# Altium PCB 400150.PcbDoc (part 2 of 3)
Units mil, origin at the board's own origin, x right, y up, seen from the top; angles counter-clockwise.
Board outline 4000 x 2500 mil, 4 copper layers (Top Layer, Mid-Layer 1, Mid-Layer 2, Bottom Layer), stack 62.293 mil thick; 200 components, 153 nets, 913 pads, 613 vias.
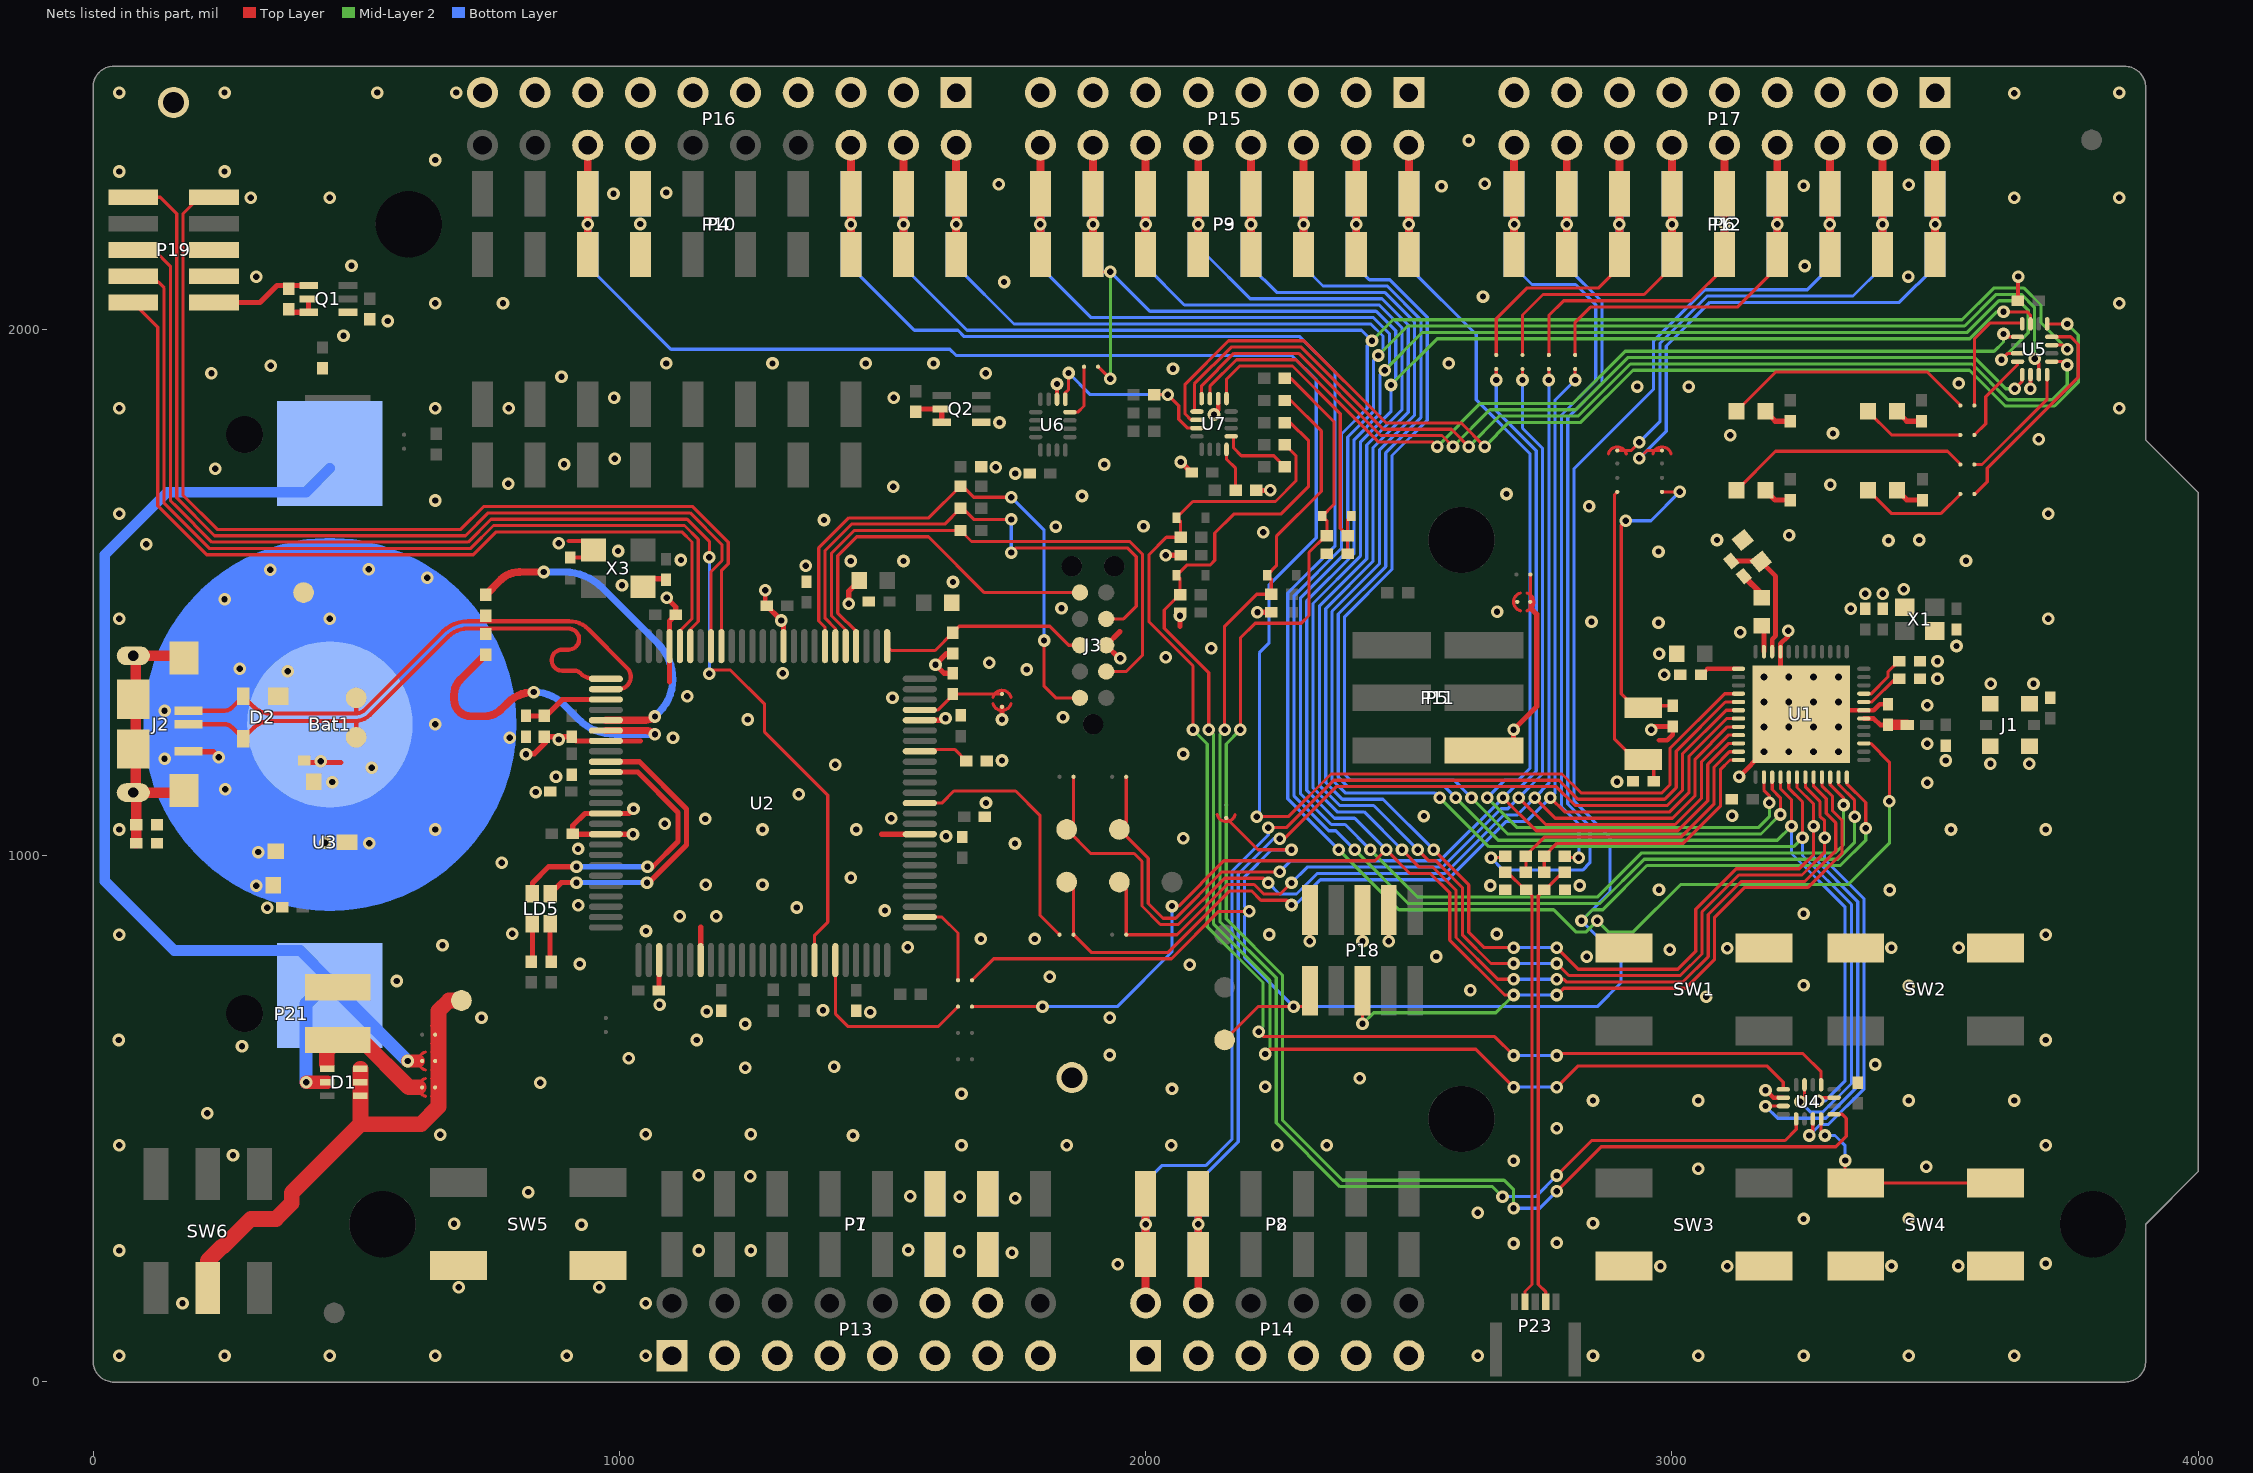
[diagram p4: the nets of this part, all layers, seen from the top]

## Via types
v1: diameter 24, hole 12, Top Layer to Bottom Layer, tented both sides, 576 vias
v2: diameter 24, hole 12, Top Layer to Bottom Layer, 21 vias
v3: diameter 25.98, hole 12.99, Top Layer to Bottom Layer, tented both sides, 16 vias

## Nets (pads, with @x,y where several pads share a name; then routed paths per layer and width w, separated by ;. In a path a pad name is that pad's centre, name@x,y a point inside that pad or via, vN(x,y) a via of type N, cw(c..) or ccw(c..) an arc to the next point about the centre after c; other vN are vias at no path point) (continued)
BUTTON4: SW4.1 U4.12 | length 425.6
  Top Layer w6: U4.12@3283.29,499.52 3283.29,475.38 v1(3290.66,468) ; v1(3329.02,420.63) 3329.02,396.63 3348.02,377.63 SW4.1@3613.77,377.63
  Bottom Layer w6: v1(3290.66,468) 3309.65,468 3329.02,448.63 v1(3329.02,420.63)
BUTTON4_EXT: C51.1 D6.3 R43.1 U7.5 | length 612.5
  Top Layer w6: U7.5@2153.56,1868.23 2153.56,1905.02 2178.53,1930 2278.99,1930 2369.75,1839.24 2369.75,1621.71 R43.1@2383.76,1607.69 ; C51.1@2383.76,1573.69 R43.1@2383.76,1607.69 ; D6.3@2390.86,1645 2383.76,1637.9 R43.1@2383.76,1607.69
CTS: SB22.2 U2.38 | length 499.2
  Top Layer w6: U2.38@1570.83,1099.6 1612.55,1099.6 1635.55,1122.6 1753.01,1122.6 1799,1076.6 1798.99,887.01 SB22.2@1836.4,849.6
DEC1: C4.1 U1.1 | length 76
  Top Layer w8: C4.1@3055.31,1342.92 3067.16,1354.77 U1.1@3126.37,1354.77
DEC2: C6.1 U1.32 | length 88.3
  Top Layer w6: U1.32@3364.56,1291.78 3379.76,1291.78 3424.14,1336.16 C6.1@3434.46,1336.16
DEC3: C7.1 U1.33 | length 96
  Top Layer w6: U1.33@3364.56,1307.53 3378.54,1307.53 3410.46,1339.46 3410.46,1349.35 C7.1@3429.52,1368.41
DEC4: C10.2 L3.1 U1.46 | length 241.3
  Top Layer w9: L3.1@3112.48,1559.49 C10.2@3167.89,1559.48 ; C10.2@3168.58,1558.8 3196.71,1530.66 3196.71,1417.47 3190.35,1411.11 U1.46@3190.35,1387.25
DFSD_N: R14.1 U2.80 | length 645
  Top Layer w13.78: 810,1538.6 v1(856.61,1538.6) ; U2.80@974.38,1257.18 1048.61,1257.18 ; 1050.33,1257.18 ccw(c1050.33,1281.62) v1@1067.61,1264.34
  Top Layer w15: R14.1@746.01,1495.22 774.82,1524.03 cw(c810,1488.84) 810,1538.6
  Bottom Layer w13.78: v1(856.61,1538.6) 896.18,1538.6 cw(c896.18,1438.6) 966.9,1509.31 1073.32,1402.88 cw(c1005.04,1334.6) 1101.61,1334.6 cw(c1013.82,1334.6) 1075.89,1272.53 v1(1067.61,1264.24)
DFSD_P: R13.1 U2.81 | length 642.8
  Top Layer w13.78: U2.81@974.38,1237.39 1049.61,1237.39 ; 1050.33,1237.39 cw(c1050.33,1212.96) v1@1067.61,1230.24
  Top Layer w15: R13.1@746.01,1382.31 697.81,1334.11 ccw(c726.32,1305.6) 686,1305.6 686,1296.6 ccw(c718,1296.6) 718,1264.6 743.64,1264.6 ccw(c743.64,1309.96) 775.71,1277.89 787.8,1289.97 cw(c837.61,1240.16) v1(837.61,1310.6)
  Bottom Layer w13.78: v1(837.61,1310.6) cw(c837.61,1230.93) 893.94,1287.27 921.68,1259.53 ccw(c992.39,1330.24) 992.39,1230.24 v1@1067.61,1230.24
  other v1: 1067.61,1230.34
DHSD_N: D2.2 J2.2 R14.2 TP2.1 U2.77 | length 1124.2
  Top Layer w8: J2.2@181.84,1275.1 249.61,1275.1 ccw(c249.61,1295.1) 263.75,1280.95 D2.2@284.82,1302.03 ; D2.2@285.2,1302.95 285.2,1302.72 305.26,1282.66 ccw(c336.68,1314.07) 336.68,1269.65 497.83,1269.65 ccw(c497.83,1296.26) 516.65,1277.44 664.24,1425.04 ; 500,1271.82 TP2.1@500,1299.6 ; 664.14,1425.14 cw(c712.81,1376.48) 712.41,1445.3 904.62,1445.3 cw(c904.62,1393.92) 940.96,1430.25 1014.68,1356.53 ; 712.43,1445.3 cw(c712.81,1376.48) 712.81,1445.3 ; U2.77@974.38,1316.13 U2.77@997.79,1316.13 ; 1014.68,1356.53 cw(c997.8,1339.64) 997.8,1315.77 ccw(c997.8,1339.64) 1014.68,1356.53
  Top Layer w13.78: D2.2@285.2,1302.95 cw(c283.89,1302.95) 284.82,1302.03 ccw(c283.89,1302.95) D2.2@285.2,1302.95
DHSD_P: D2.3 J2.3 R13.2 TP1.1 U2.76 | length 1102.6
  Top Layer w8: J2.3@181.84,1249.6 249.61,1249.6 cw(c249.61,1229.6) 263.75,1243.74 D2.3@285.2,1222.25 ; D2.3@285.2,1222.49 305.26,1242.55 ; TP1.1@500,1224.6 500,1253.17 ; 674.57,1415.53 cw(c712.41,1377.7) 674.78,1415.73 cw(c712.41,1377.7) 712.41,1431.2 904.91,1431.2 ; 674.98,1415.93 526.62,1267.58 cw(c497.61,1296.6) 497.61,1255.56 336.67,1255.56 ; 891.42,1351.1 cw(c891.42,1371.1) 891.42,1391.1 ; 891.61,1351.1 915.35,1351.1 cw(c915.35,1337.44) 925.01,1347.1 ccw(c952.24,1374.33) 952.24,1335.82 U2.76@974.38,1335.82 ; 891.81,1391.1 903.62,1391.1 ccw(c903.62,1411.1) 903.62,1431.1 ; 305.26,1242.55 cw(c336.67,1211.13) 336.67,1255.56 ; 305.26,1242.55 cw(c336.67,1211.13) 336.67,1255.56
  Top Layer w13.78: D2.3@285.2,1222.25 D2.3@285.2,1222.49
EXT_GND_DETECT: P19.9 U2.67 | length 1918.7
  Top Layer w6: P19.9@229.77,2250.6 202,2250.6 171,2219.6 171,1684.48 235.88,1619.6 698.56,1619.6 742,1663.04 1139.52,1663.04 1207,1595.55 1207,1554.43 1193.87,1541.3 U2.67@1193.87,1397.83
EXT_RESET: P19.10 U2.68 | length 1946.2
  Top Layer w6: P19.10@76.23,2250.6 128,2250.6 159,2219.6 159,1679.51 230.91,1607.6 707.65,1607.6 751.09,1651.04 1134.55,1651.04 1195,1590.58 1195,1560.32 1174.18,1539.5 U2.68@1174.18,1397.83 U2.68@1174,1398.01
EXT_SWDCLK: P19.4 U2.70 | length 1765.6
  Top Layer w6: P19.4@76.23,2100.6 113,2100.6 135,2078.6 135,1669.57 220.97,1583.6 717.59,1583.6 761.03,1627.04 1123.76,1627.04 1150,1600.79 1150,1444.63 1134.81,1429.44 U2.70@1134.81,1397.83
EXT_SWDIO: P19.2 U2.71 | length 1692.3
  Top Layer w6: P19.2@76.23,2050.6 123,2003.83 123,1664.6 216,1571.6 722.56,1571.6 766,1615.04 1118.78,1615.04 1138,1595.82 1138,1449.6 1115.13,1426.73 U2.71@1115.13,1397.83
EXT_SWO: P19.6 U2.18 | length 2553.2
  Top Layer w6: P19.6@76.23,2150.6 116,2150.6 147,2119.6 147,1674.54 158.94,1662.6 225.94,1595.6 712.62,1595.6 756.06,1639.04 1128.78,1639.04 1171,1596.82 v1(1171,1566.92) ; v1(1171,1345.6) 1178,1352.6 1211,1352.6 1276,1287.6 1276,1234.6 1396,1114.6 1396,873.6 1371.03,848.63 U2.18@1371.03,801.37
  Bottom Layer w6: v1(1171,1345.6) v1(1171,1566.92)
EXT_VTG: P19.1 Q1.4 R8.1 | length 193.3
  Top Layer w10: P19.1@229.77,2050.6 317,2050.6 349.59,2083.19 Q1.4@409.6,2083.19
GND: Bat1.2 C1.2 C2.2 C3.1 C4.2 C5.2 C6.2 C7.2 C8.2 C9.2 C10.1 C11.1 C12.1 C13.2 C15.2 C16.1 C17.1 C18.1 C19.1 C20.1 C21.1 C22.2 C23.2 C24.1 C25.1 C26.1 C27.1 C28.1 C29.1 C30.1 C31.1 C32.1 C33.1 C34.1 C35.1 C36.2 C37.1 C38.1 C39.1 C40.1 C41.1 C42.2 C43.1 C44.1 C45.1 C46.1 C47.1 C48.2 C49.1 C50.1 C51.2 D2.1 J1.2 J2.5 J3.3 P1.6 P1.7 P4.7 P7.6 P7.7 P10.7 P13.1 P13.3 P13.5 P13.7 P13.9 P13.11 P13.12 P13.13 P13.14 P13.15 P14.1 P14.3 P14.5 P14.7 P14.9 P14.11 P15.1 P15.3 P15.5 P15.7 P15.9 P15.11 P15.13 P15.15 P16.1 P16.3 P16.5 P16.7 P16.9 P16.11 P16.13 P16.14 P16.15 P16.17 P16.19 P17.1 P17.3 P17.5 P17.7 P17.9 P17.11 P17.13 P17.15 P17.17 P18.3 P18.5 P18.9 P19.3 P19.5 P21.1 Q1.1 Q2.1 R7.2 R10.1 R11.1 R12.1 R17.1 R18.1 R24.2 R38.1 SB18.1 SB28.2 SW1.2 SW2.2 SW3.2 SW4.2 SW5.2 TP4.1 TP12.1 TP13.1 U1.31 U1.45 U1.49 U2.3 U2.7 U2.35 U2.46 U2.61 U2.72 U2.82 U2.89 U2.91 U3.3 U4.6 U5.6 U6.6 U7.6 X1.2 X1.4 X3.2 X3.4 | length 2504.2
  Top Layer w8: 904,1597.6 933.66,1597.6 X3.2@950.6,1580.66 936.22,1566.28 C22.2@906.61,1566.28 ; U6.6@1831.49,1867 v1(1831.49,1896) ; v1(2129.94,1838) 2137.81,1845.87 U7.6@2137.81,1868.23 ; v1(2312,837) P18.9@2312,896.54 ; v1(2412,837) P18.5@2412,896.54 ; v1(2462,837) P18.3@2462,896.54 ; v1(3177.66,554) 3178.78,554 3192.9,539.87 U4.6@3211.44,539.87 ; C45.1@3657.31,2054 v1@3657.31,2099.63 ; v1(3681,1887) 3681.13,1887.13 U5.6@3681.13,1913.77
  Top Layer w9: v1(1277,1503.92) 1277,1477.52 C35.1@1279.92,1474.6 ; v1(1727,1258.49) 1727,1275.62 SB28.2@1727,1282.49 ; v1(2960.61,1238.85) 2966.93,1245.16 C11.1@3001.61,1245.16 3001.61,1229.54 2990.91,1218.85 2975.14,1218.85 ; v1(3127.46,1150.05) 3127.46,1150.16 v3(3174.6,1197.29) U1.49@3245.46,1268.16 ; U1.49@3206.09,1354.77 U1.45@3206.09,1387.25 3206.09,1402.08 3221,1416.99 v1(3221,1426.8) 3218.76,1424.55 v1@3217.56,1424.55 ; U1.49@3269.78,1276.16 3383.23,1276.16 3394.53,1287.46 C3.1@3410.78,1287.46
  Top Layer w10: J2.5@186.84,1198.42 186.84,1197.1 228.46,1197.1 v2(239,1186.56) ; C21.1@401.29,1180.6 401.29,1176.6 471.11,1176.6 ; v1@827.61,1193.6 838.61,1193.6 860.61,1215.6 860.61,1225.91 C38.1@909.61,1225.91 917.81,1217.71 U2.82@974.38,1217.71 1039.89,1217.71 ; v1(1026,1040.6) v1(1026,1040.6) U2.91@974.38,1040.54 912.35,1040.54 C41.1@911.29,1041.6 911.29,1056.66 934.55,1079.91 U2.89@974.38,1079.91 1018.31,1079.91 v1(1027,1088.6) ; X3.4@1044.61,1525.91 C23.2@1088.61,1525.91 ; C24.1@1075.29,743.6 U2.3@1075.29,800.91 ; v1(1090,1489.6) 1107.29,1472.31 C36.2@1107.29,1457.6 1095.44,1445.75 U2.72@1095.44,1397.83 1095.44,1330.04 ; U2.7@1154.5,801.37 1154.5,864.1 ; C35.1@1279.92,1474.6 v1@1305.92,1448.6 ; U2.61@1311.98,1397.83 v1@1311.98,1440.36 ; v1(1436,1478.6) 1436,1502.57 C33.1@1456.03,1522.6 ; 1498.06,1040.54 U2.35@1570.83,1040.54 ; U2.46@1570.83,1257.08 1616.09,1257.08 v1(1619.61,1260.6) ; C30.1@1633.61,1346.28 1616.92,1346.28 v1(1600.61,1362.6) 1621.92,1383.91 R24.2@1633.61,1383.91 ; 1951,1425.6 J3.3@1925,1399.6 1950,1374.6 v1(1952,1374.6) ; v1(2038.31,1570.77) C48.2@2066.31,1570.77 ; 2065.31,1435.77 2065.31,1461.69 C49.1@2065.39,1461.77 ; v1(2066.62,1747.77) 2067.31,1747.77 C47.1@2087.31,1727.77 ; R38.1@2210.36,1693.77 v1(2236.62,1693.77) ; v1(2212.31,1462.47) C50.1@2238.62,1462.47
  other v1: 50,49.6 250,49.6 450,49.6 650,49.6 900,49.6 1050,49.6 2631,49.6 2850,49.6 3050,49.6 3250,49.6 3450,49.6 3650,49.6 170,149.6 1050,149.6 695,179.6 962,179.6 2978.02,219.71 3105.02,219.71 3417.02,220.15 3544.02,220.15 1947,223.6 3710,225 1746,245.6 1646,247.6 50,249.6 1151,249.6 1250,249.6 1549,250.6 2699,263 2781,264 928,298.6 686,300.6 2850,301.6 3250,309.6 3450,309.6 2631,321.6 1752,348.6 1647,351.6 1553,352.6 827,360.6 1249,390.6 1151,392.6 3050.02,404.64 3482.89,408.89 2699,420 266,430.6 50,449.6 1650,449.6 1850,449.6 2048.5,449.6 2250,449.6 2344,449.6 3710,449.6 1444,468 660,469.6 1050,470.6 1250,470.6 2781,482 217,510.6 2850,534.6 3050,534.6 3450,534.6 3650,534.6 1650,547.6 2050,556.6 2227,561 850,568.6 2406.69,577 1239,596.6 1408.02,599 3386,603 1018,614.92 1932.02,621 283,637.6 49,649.6 1147,649.6 3710,649.6 1239.02,680 738,691.6 1932.02,692 1477,702.6 1166,703.6 1387.02,706 1076.44,716.37 3065,732 2617,744 3450,752.6 3250,753.6 577,761.6 1818,769.6 2084,792.6 924.61,793.91 2552,808.23 2838,808 2996,821 3105,824 3416.87,824.74 3544.87,824.74 1548.2,825.6 664,829.6 1687,841.6 1789,841.6 50,849.6 2235,850 3710,849.6 2667,851 796.61,851.6 1050.61,856.6 1115,884.6 1184,884.6 3250,889.6 1504.61,895.6 331,900.6 1337.09,901.37 922,905.6 2975.31,935 3414,934.6 2655,943 2825,943 1164,944.6 1272,944.6 1440,957.6 776.61,986.6 921.61,1012.6 1751.69,1023 2071.31,1033 1620.61,1036.6 50,1049.6 1272,1049.6 1450,1049.6 3530,1049.6 3710,1049.6 1086,1060.6 1163,1069.6 1516.61,1070.6 2528.69,1075 3114.13,1075.74 1696.69,1100 1341.09,1116.37 841,1120.6 3485,1138.03 2895.5,1140.29 879.61,1149.6 1410.09,1172.37 3605,1174.6 3679,1174.6 1727,1180.6 3520,1180.6 822.61,1192.6 2071.31,1193 3485,1212.6 884.61,1220.6 1102,1223.6 1244,1258.6 1843,1262.6 3485,1285.6 1519,1299.6 1129,1302.6 3605.87,1326.16 3686.87,1326.16 3504.46,1336.16 2985.46,1343.37 1310.61,1346.6 1774,1353.6 1703,1366.6 3504.46,1369.16 2038.31,1377 2975.46,1383.37 2124.31,1394 3540.46,1398.16 3129.46,1423.96 2974.46,1442.54 2847,1444 1307.61,1446.6 50,1449.6 3715,1449.6 2065.31,1455.77 2667.69,1463 3339.46,1469.16 1840,1469.6 3367.46,1497.54 3400.46,1497.54 3440.46,1506.16 1005,1513.6 1634,1519.6 1354,1550.6 1439.61,1559.6 1540,1559.6 3558.46,1560.16 1117,1561.6 2974.46,1577.54 997.61,1578.6 101,1591.6 884.61,1593.6 3411.46,1598.54 3085.46,1599.54 3470,1599.6 3222.46,1608.54 2223.31,1614 1829.31,1625 1996,1625.6 1388.84,1637.6 50,1649.6 3715,1649.6 2842.46,1663.54 650,1674.6 1879.09,1683 2685.69,1687 1520.31,1700.77 3301,1704.6 789,1706.6 1752.31,1725.77 232,1734.6 1715.31,1737.77 1921.09,1743 895,1743.6 991,1753.6 3696.69,1791 3110.46,1798.54 3306.01,1801.99 1722.31,1822.77 50,1849.6 650,1849.6 790,1849.6 3850,1849.6 990,1869.6 1521.31,1869.77 2933.69,1891 3031.69,1891 3545.01,1896.99 890,1909.6 225,1916.6 1696,1916.6 2052,1925 338,1930.6 1089,1935 1291,1935 1468,1935 1597,1935 2576,1935 476,1987.6 560,2015.6 650,2049.6 779,2049.6 3850,2049.6 2641,2062 1731,2089.6 310,2099.6 3449,2100 3657.69,2100 3252,2120 491,2120.6 1040,2200 300,2249.6 450,2249.6 3650,2249.6 3850,2249.6 989,2257.6 1089,2259.6 2562,2271.6 3250,2272.6 3450,2274.6 1721,2275.6 2644,2276.6 50,2299.6 250,2299.6 650,2321.6 2614,2358.6 3650,2448.6 50,2449.6 250,2449.6 540,2449.6 690,2449.6 3850,2449.6
  other v2: 310,942.6 314,1006.6 525,1023.6 441,1024.6 650,1049.6 251,1126 454.61,1139.6 529.61,1166.6 432.61,1179.1 136,1184 791.61,1223.6 650,1249.6 136,1275 370,1350 279,1355 450,1449.6 250,1487 635,1528 337,1543 524,1544
  other v3: 3221.84,1197.29 3269.09,1197.29 3316.33,1197.29 3174.6,1244.54 3221.84,1244.54 3269.09,1244.54 3316.33,1244.54 3174.6,1291.78 3221.84,1291.78 3269.09,1291.78 3316.33,1291.78 3174.6,1339.03 3221.84,1339.03 3269.09,1339.03 3316.33,1339.03
IMCU_RESET: J3.10 R23.1 U2.57 | length 1076.3
  Top Layer w6: U2.57@1390.72,1397.83 1390.72,1434.02 1379,1445.73 1379,1584.51 1436.09,1641.6 1588.16,1641.6 R23.1@1648.16,1701.6 1652.16,1701.6 1673.16,1680.6 v1(1744.69,1680.6) ; v1(1807,1408.6) 1807,1321.6 1829,1299.6 J3.10@1875,1299.6
  Bottom Layer w6: v1(1744.69,1680.6) 1807,1618.29 v1(1807,1408.6)
IMCU_TCKS: J3.4 R22.1 U2.56 | length 1057.3
  Top Layer w6: U2.56@1410.4,1397.83 1410.4,1431.3 1391,1450.7 1391,1579.54 1441.06,1629.6 1618.16,1629.6 R22.1@1648.16,1659.6 1652.16,1659.6 1673.16,1638.6 v1(1744.69,1638.6) ; v1(1744.69,1575.6) 1753.69,1584.6 1965.03,1584.6 1982,1567.63 1982,1473.6 1958,1449.6 J3.4@1925,1449.6
  Bottom Layer w6: v1(1744.69,1575.6) v1(1744.69,1638.6)
IMCU_TDIS: J3.8 R24.1 U2.51 | length 403.5
  Top Layer w6: U2.51@1508.83,1397.83 1517.05,1389.6 1599.92,1389.6 R24.1@1633.61,1423.28 1645.92,1435.6 1818,1435.6 1854,1399.6 J3.8@1875,1399.6
IMCU_TDOS: J3.6 U2.54 | length 705
  Top Layer w6: U2.54@1449.77,1397.83 1449.77,1425.87 1415,1460.64 1415,1569.6 1451,1605.6 1587.48,1605.6 1693.48,1499.6 J3.6@1875,1499.6
IMCU_TMSS: J3.2 R21.1 U2.55 | length 1089.2
  Top Layer w6: U2.55@1430.09,1397.83 1430.09,1428.59 1403,1455.67 1403,1574.57 1446.03,1617.6 R21.1@1648.16,1617.6 1669.16,1596.6 1969.84,1596.6 ; J3.2@1925,1349.6 1963,1349.6 1994,1380.6 1994,1572.6 1969.92,1596.68
INT_EXT: R31.1 U6.5 U7.11 | length 380.4
  Top Layer w6: U6.5@1847.24,1867 1847.24,1879.24 1853.52,1885.52 v1(1853.52,1916.77) ; R31.1@2016.31,1875.77 v1(2041.94,1875.77) 2062.94,1854.77 2062.94,1829 2079.81,1812.13 U7.11@2097.45,1812.13
  Bottom Layer w6: v1(1853.52,1916.77) 1894.52,1875.77 v1(2041.94,1875.77)
LED1: SB5.1 U5.16 | length 229.6
  Top Layer w6: SB5.1@3574.5,1855 3574.5,1981.5 3605,2012 U5.16@3665,2012
LED1_EXT: U5.1 U7.7 | length 1744.6
  Top Layer w6: U7.7@2122.06,1868.23 2122.06,1891.38 2172.68,1942 2285.71,1942 2441.71,1786 2545,1786 v1(2554,1777) ; v1(3629.94,1991) 3635.32,1985.62 U5.1@3656.52,1985.62
  Mid-Layer 2 w6: v1(2554,1777) 2636,1859 2812,1859 2911,1958 3612,1958 3629.75,1975.75 v1@3629.75,1989.07
LED2: SB6.1 U5.4 | length 173.4
  Top Layer w6: SB6.1@3574.5,1799 3596,1820.5 3596,1871.71 3656.52,1932.23 U5.4@3656.52,1938.38
LED2_EXT: U5.5 U7.8 | length 1795
  Top Layer w6: U7.8@2106.31,1868.23 2106.31,1892.63 2167.68,1954 2290.68,1954 2446.68,1798 2563,1798 v1(2584,1777) ; v1(3651,1887) 3665.38,1901.38 U5.5@3665.38,1913.77
  Mid-Layer 2 w6: v1(2584,1777) 2654,1847 2816.97,1847 2915.97,1946 3575.2,1946 3634.2,1887 v1(3651,1887)
LED3: SB7.1 U5.8 | length 236.5
  Top Layer w6: SB7.1@3574.5,1743 3589,1743 3712.62,1866.62 U5.8@3712.62,1913.77
LED3_EXT: U5.9 U7.9 | length 1992.5
  Top Layer w6: U7.9@2092.53,1843.77 2092.53,1896.23 2162.31,1966 2295.65,1966 2451.65,1810 2581,1810 v1(2614,1777) ; U5.9@3721.48,1938.38 3744.62,1938.38 v1(3751,1932)
  Mid-Layer 2 w6: v1(2614,1777) 2672,1835 2821.94,1835 2920.94,1934 3570.23,1934 3638.23,1866 3722,1866 3751,1895 v1(3751,1932)
LED4: SB8.1 U5.12 | length 422.4
  Top Layer w6: SB8.1@3575.46,1686.54 3599,1710.07 3599,1736.03 3772,1909.03 3772,1971 3757.38,1985.62 U5.12@3721.48,1985.62
LED4_EXT: U5.13 U7.10 | length 2163
  Top Layer w6: U7.10@2097.45,1827.87 2085.89,1827.87 2074.94,1838.82 2074.94,1895.63 2157.31,1978 2300.62,1978 2456.62,1822 2599,1822 v1(2644,1777) ; U5.13@3712.62,2010.23 v1@3750.77,2010.23
  Mid-Layer 2 w6: v1(2644,1777) 2690,1823 2826.91,1823 2925.91,1922 3565.26,1922 3633.26,1854 3726.97,1854 3772,1899.03 3772,1989 v1(3751,2010)
NetBat1_1: Bat1.1 D1.5 SB11.2 | length 2110.2
  Top Layer w25: v1(405,569.19) D1.5@445.01,569.19 ; v1(598,609.6) 618.53,609.6
  Bottom Layer w20: Bat1.1@449.9,763.38 393.69,819.6 154,819.6 22,951.6 22,1571.6 141,1690.6 404.68,1690.6 Bat1.1@449.9,1735.82
  Bottom Layer w25: v1(405,569.19) 405,718.48 449.9,763.38 449.9,757.7 v1(598,609.6)
NetC3_2: C3.2 L1.1 U1.30 | length 86.6
  Top Layer w9: U1.30@3364.56,1260.29 3383.26,1260.29 3395.46,1248.09 C3.2@3410.78,1248.09
  Top Layer w20: C3.2@3410.46,1248.29 L1.1@3445.78,1248.29
NetC11_2: C11.2 SB2.1 X2.1 | length 602.3
  Top Layer w6: v1(2912,1636) 2903.46,1627.46 2903.46,1307.54 2929.94,1281.06 X2.1@2945.61,1281.06 2949.08,1284.53 C11.2@3001.61,1284.53 ; SB2.1@2981,1691 v1(3015,1691)
  Bottom Layer w6: v1(2912,1636) 2960,1636 v1(3015,1691)
NetC12_2: C12.2 SB1.1 X2.2 | length 592.5
  Top Layer w6: SB1.1@2896,1691 2891,1686 2891,1221 2929.37,1182.63 X2.2@2945.61,1182.63 2965.3,1162.95 C12.2@2965.3,1140.85
NetC19_2: C19.2 J2.6@76.53,1119.68 J2.6@76.53,1202.36 J2.6@76.53,1296.84 J2.6@76.53,1379.52 J2.6@172.98,1123.62 J2.6@172.98,1375.58 R12.2 | length 552.4
  Top Layer w20: C19.2@82.16,1023.6 82.16,1119.05 J2.6@81.53,1119.68 ; J2.6@177.98,1123.62 174.05,1119.68 J2.6@81.53,1119.68 ; J2.6@177.98,1375.58 174.05,1379.52 81.53,1379.52 81.53,1296.84 81.53,1202.36 J2.6@81.53,1119.68
NetC30_2: C30.2 SB28.1 U2.47 | length 170
  Top Layer w6: U2.47@1570.83,1276.76 1605.68,1276.76 1633.61,1304.69 C30.2@1633.61,1306.91 1712.97,1306.91 1726.83,1306.91 SB28.1@1727,1307.09
NetC37_2: C37.2 R17.2 U2.78 | length 161.7
  Top Layer w10: C37.2@825.61,1265.28 860.61,1265.28 891.77,1296.45 U2.78@974.38,1296.45
NetD1_1: D1.1 D1.2 D1.3 SB10.1 SB11.1 SB12.1 SW6.2 TP14.1 | length 961.6
  Top Layer w30: SW6.2@218,178.33 218,229.99 245.52,257.51 247.91,257.51 300,309.6 347.43,309.6 377.58,339.75 377.58,359.18 508,489.6 ; D1.3@508,594.78 D1.2@508,569.19 D1.1@508,543.6 508,489.6 ; TP14.1@700,724.6 676.2,724.6 656.2,704.6 656.2,522.8 623,489.6 508,489.6
NetD1_4: D1.4 P21.2 SB12.2 | length 245.5
  Top Layer w30: 444,603.6 444,628.6 P21.2@465,649.6 510,649.6 600,559.6 618.53,559.6
NetD3_1: D3.1 R33.1 R40.2 U4.1 | length 2575
  Top Layer w6: v1(2090,1239) 2090,1360.29 2006.31,1443.98 2006.31,1571.77 2039.3,1604.77 2066.3,1604.77 2066.31,1634.13 D3.1@2058.66,1641.77 2089.66,1672.77 2246.62,1672.77 2285.62,1711.77 2285.62,1759.62 R33.1@2264.62,1780.62 ; v1(2215,665) 2224,656 2662.99,656 v1(2699,620) ; v1(2781,620) 2785,624 3248.69,624 3283.29,589.41 U4.1@3283.29,564.48
  Mid-Layer 2 w6: v1(2090,1239) 2117,1212 2117,864.85 2223,758.85 2223,674 2215,666 v1(2215,665)
  Bottom Layer w6: v1(2699,620) v1(2781,620)
NetD4_1: D4.1 R34.1 R41.2 U4.5 | length 2570
  Top Layer w6: R41.2@2064.75,1496.07 2035.31,1466.63 2035.31,1431.98 2120,1347.29 v1(2120,1239) ; R41.2@2065.39,1495.77 2065.39,1526.13 D4.1@2058.75,1532.77 2077.75,1551.77 2122.31,1551.77 2131.31,1560.77 2131.31,1612.77 2167.31,1648.77 2256.82,1648.77 2309.62,1701.57 2309.62,1787.96 2274.96,1822.62 R34.1@2264.62,1822.62 ; v1(2227,623) 2236,632 2626.99,632 v1(2699,560) ; v1(2781,560) 2821,600 3181.02,600 3211.44,569.58 U4.5@3211.44,555.62
  Mid-Layer 2 w6: v1(2120,1239) 2129,1230 2129,869.82 2236,762.82 2236,632 v1(2227,623)
  Bottom Layer w6: v1(2699,560) v1(2781,560)
NetD5_1: D5.1 R35.1 R42.2 U4.9 | length 2673.4
  Top Layer w6: v1(2150,1239) 2150,1435.69 2210.77,1496.47 R42.2@2238.62,1496.47 2238.62,1524.9 D5.1@2230.75,1532.77 2248.31,1550.33 2248.31,1606.31 2333.62,1691.63 2333.62,1806.74 2275.74,1864.62 R35.1@2264.62,1864.62 ; v1(2781,392) 2847.63,458.63 3215.02,458.63 3236.04,479.66 U4.9@3236.04,499.52
  Mid-Layer 2 w6: v1(2150,1239) 2141,1230 2141,874.79 2248,767.79 2248,492.03 2369.03,371 2658.99,371 v1(2678,352)
  Bottom Layer w6: v1(2678,352) 2741,352 v1(2781,392)
NetD6_1: D6.1 R36.1 R43.2 U4.13 | length 2917.8
  Top Layer w6: v1(2180,1239) 2180,1413.25 2208.21,1441.47 2295.77,1441.47 2310.31,1456 2310.31,1576 R43.2@2341.31,1607 ; R36.1@2264.62,1906.62 2275.74,1906.62 2357.62,1824.74 2357.62,1666.87 D6.1@2335.75,1645 2344.39,1636.35 R43.2@2344.39,1607.69 ; v1(2781,362) 2865.63,446.63 3311.02,446.63 3331.02,466.63 3331.02,500.63 3323.27,508.38 U4.13@3307.89,508.38
  Mid-Layer 2 w6: v1(2180,1239) 2153,1212 2153,879.76 2260,772.76 2260,497 2374,383 2680.99,383 2699,365 v1(2699,330)
  Bottom Layer w6: v1(2699,330) 2749,330 v1(2781,362)
NetL2_1: L2.1 L3.2 | length 55.2
  Top Layer w11: L3.2@3136.52,1530.83 3170.46,1496.88 L2.1@3170.46,1489.73
NetL2_2: L2.2 U1.47 | length 42.4
  Top Layer w9: U1.47@3174.6,1387.25 L2.2@3174.6,1429.7
NetLD5_1: LD5.1 R20.1 | length 71.8
  Top Layer w10: R20.1@834.87,798.28 LD5.1@834.87,870.06
NetLD5_2: LD5.2 R19.1 | length 71.8
  Top Layer w10: R19.1@868.34,798.28 LD5.2@868.34,870.06
NetLED1_1: LED1.1 SB5.2 | length 483.5
  Top Layer w6: LED1.1@3122.51,1843.99 3197.51,1918.99 3484.41,1918.99 SB5.2@3548.41,1854.99
NetLED1_2: LED1.2 R1.1 | length 55.2
  Top Layer w10: LED1.2@3177.51,1843.99 3196.19,1825.31 R1.1@3225.01,1825.31
NetLED2_1: LED2.1 SB6.2 | length 194.3
  Top Layer w6: LED2.1@3372.25,1844 3417.25,1799 SB6.2@3547.9,1799
NetLED2_2: LED2.2 R2.1 | length 54
  Top Layer w10: LED2.2@3427.25,1844 3445.94,1825.31 R2.1@3473.5,1825.31
NetLED3_1: LED3.1 SB7.2 | length 467.6
  Top Layer w6: LED3.1@3121.75,1693 3196.76,1768 3522.9,1768 ; 3523.41,1767.99 SB7.2@3548.41,1742.99
NetLED3_2: LED3.2 R3.1 | length 55
  Top Layer w10: LED3.2@3177.25,1694 3195.94,1675.31 R3.1@3224.5,1675.31
NetLED4_1: LED4.1 SB8.2 | length 208.9
  Top Layer w6: LED4.1@3372.51,1693.99 3416.5,1650 3510.9,1650 ; 3511.41,1649.99 SB8.2@3548.41,1686.99
NetLED4_2: LED4.2 R4.1 | length 55.7
  Top Layer w10: LED4.2@3427.51,1693.99 3446.19,1675.31 R4.1@3475.5,1675.31
NetP5_6: P5.6 P11.6 SB18.2 SB19.1 | length 396.7
  Top Layer w6: SB18.2@2731,1479.4 2731,1495.59 SB19.1@2731,1534
  Top Layer w10: P5.6@2699,1201.6 v1(2699,1239) 2743,1283 2743,1458.29 2732,1469.29 2732,1478.4 2735.6,1482
  Bottom Layer w10: P11.6@2699,1201.6 v1(2699,1239)
NetQ1_5: Q1.5 Q1.6 R8.2 | length 65.6
  Top Layer w10: R8.2@372,2037.91 377.91,2032.01 Q1.6@409.6,2032.01 Q1.5@409.6,2057.6
NetQ2_5: Q2.5 Q2.6 R9.2 | length 77.5
  Top Layer w10: R9.2@1563,1842.91 1568.69,1848.6 Q2.5@1612.6,1848.6 Q2.6@1612.6,1823.01
NetR18_2: R18.2 U2.43 | length 98.7
  Top Layer w6: U2.43@1570.83,1198.02 1574.41,1201.6 1636.92,1201.6 R18.2@1658.92,1179.6
NetR32_1: R32.1 U7.1 | length 135.8
  Top Layer w6: U7.1@2166.89,1796.62 2166.89,1774.67 2181.94,1759.62 2243.61,1759.62 R32.1@2264.62,1738.62 R32.1@2265.77,1738.62
NetR37_1: R37.1 R38.2 U7.16 | length 85.2
  Top Layer w6: U7.16@2153.56,1771.77 2153.56,1753 2170.99,1735.57 R38.2@2170.99,1693.77
NetSB30_2: SB30.2 U6.4 | length 106.3
  Top Layer w6: U6.4@1856.1,1842.39 1871.14,1842.39 1882.92,1854.17 SB30.2@1882.92,1928.77
NFC1: C42.1 P23.2 R25.1 | length 846.6
  Top Layer w6: R25.1@2683.16,968.6 2687.16,968.6 2720.77,935 C42.1@2722.68,935 2734,923.68 2734,185 2720.68,171.68 P23.2@2720.68,152
NFC2: C43.2 P23.4 R26.1 | length 846.6
  Top Layer w6: P23.4@2760.05,152 2760.05,170.94 2746,185 2746,923.68 C43.2@2757.31,935 2758.92,935 2792.52,968.6 R26.1@2796.53,968.6
NRF_RESET: SB27.2 U2.27 | length 174.9
  Top Layer w6: U2.27@1570.83,883.06 1613.09,883.06 1643.42,852.74 SB27.2@1643.42,763
NRF_SWO: SB26.2 U2.20 | length 360.7
  Top Layer w6: U2.20@1410.4,801.37 1410.4,699.61 1435.02,675 1605.42,675 SB26.2@1643.42,713
OB_LED1: LD5.4 U2.84 | length 556.7
  Top Layer w10: LD5.4@868.34,927.14 889.79,948.6 v1(918.61,948.6) ; U2.84@974.38,1178.34 1037.87,1178.34 1127.61,1088.6 1127.61,1020.07 1056.13,948.6 v1(1052.61,948.6)
  Bottom Layer w10: v1(918.61,948.6) v1(1052.61,948.6)
OB_LED2: LD5.3 U2.85 | length 554.4
  Top Layer w10: LD5.3@834.87,927.14 834.87,947.87 865.61,978.6 v1(918.61,978.6) ; U2.85@974.38,1158.65 1034.92,1158.65 1111.61,1081.97 1111.61,1026.7 1063.51,978.6 v1(1053.61,978.6)
  Bottom Layer w10: v1(918.61,978.6) v1(1053.61,978.6)
P0.00: P6.1 P12.1 P17.2 SB4.2 | length 1202.7
  Top Layer w6: v1(2938,1755) 2952.6,1769.6 SB4.2@2981,1769.6
  Top Layer w15: P6.1@3500,2141.92 v1(3500,2199.6) P6.1@3500,2257.28 P17.2@3500,2349.6
  Bottom Layer w6: v1(2938,1755) 2989,1806 2989,1968 3072,2051 3432,2051 3500,2119 P12.1@3500,2141.92
  Bottom Layer w15: P12.1@3500,2141.92 v1(3500,2199.6) P12.1@3500,2257.28
P0.01: P6.2 P12.2 P17.4 SB3.2 | length 1081.9
  Top Layer w6: SB3.2@2896,1769.6 2922.6,1769.6 v1(2938,1785)
  Top Layer w15: P6.2@3400,2141.92 v1(3400,2199.6) P6.2@3400,2257.28 P17.4@3400,2349.6
  Bottom Layer w6: v1(2938,1785) 2977,1824 2977,1972.97 3067.03,2063 3344,2063 3400,2119 P12.2@3400,2141.92
  Bottom Layer w15: P12.2@3400,2141.92 v1(3400,2199.6) P12.2@3400,2257.28
P0.02: P4.8 P10.8 P16.16 U1.4 | length 3822
  Top Layer w6: v1(2211,1074) 2271.12,1074 2352.12,1155 2791,1155 2827,1119 2981.01,1119 2996,1133.99 2996,1203.3 3100.23,1307.53 U1.4@3126.37,1307.53
  Top Layer w15: P4.8@940,2141.92 v1(940,2199.6) P4.8@940,2257.28 P16.16@940,2349.6
  Bottom Layer w6: P10.8@940,2141.92 940,2120 1098,1962 1628.06,1962 1640.06,1950 2277.71,1950 2324,1903.71 2324,1799 ; v1(2211,1074) 2216,1079 2216,1385 2234,1403 2234,1513.65 2324,1603.65 2324,1821.08
  Bottom Layer w15: P10.8@940,2119.6 v1(940,2199.6) P10.8@940,2257.28
P0.03: P2.1 P8.1 P14.2 U1.5 | length 2226.9
  Top Layer w6: v1(2233,1053) 2267.1,1053 2357.1,1143 2785.22,1143 2821.22,1107 2986.01,1107 3008,1128.99 3008,1198.3 3101.48,1291.78 U1.5@3126.37,1291.78
  Top Layer w15: P14.2@2000,149.6 P2.1@2000,241.92 v1(2000,299.6) P2.1@2000,357.28
  Bottom Layer w6: P8.1@2000,380.6 2030.23,410.83 2113.83,410.83 2164,461 2164,970 2233,1039 v1(2233,1053)
  Bottom Layer w15: P8.1@2000,241.92 v1(2000,299.6) P8.1@2000,380.6
P0.04: P2.2 P8.2 P14.4 U1.6 | length 2111.9
  Top Layer w6: v1(2255,1032) 2263.07,1032 2362.07,1131 2780.22,1131 2816.22,1095 2991.01,1095 3020,1123.99 3020,1193.3 3102.73,1276.03 U1.6@3126.37,1276.03
  Top Layer w15: P14.4@2100,149.6 P2.2@2100,241.92 v1(2100,299.6) P2.2@2100,357.28
  Bottom Layer w6: P8.2@2100,357.28 2100,380 2176,456 2176,965.03 2242.97,1032 v1(2255,1032)
  Bottom Layer w15: P8.2@2100,241.92 v1(2100,299.6) P8.2@2100,357.28
P0.05: SB13.2 SB22.1 TP5.1 U1.7 | length 2467.4
  Top Layer w6: TP5.1@1863,936.6 SB22.1@1863,849.6 1896.6,816 2043,816 2159.94,932.94 2201.06,932.94 2219,915 2268,915 v1(2277,906) ; v1(2769,1110) 2796,1083 2996.01,1083 3032,1118.99 3032,1188.18 3104.1,1260.29 U1.7@3126.37,1260.29 ; v1(2816,1903.4) SB13.2@2816,1924.4
  Bottom Layer w6: v1(2277,906) 2284,906 2332,954 2574,954 2685,1065 2724,1065 v1(2769,1110) 2778,1119 2778,1865.4 v1(2816,1903.4)
P0.05_C: P6.4 P12.4 P17.8 SB13.1 | length 826.8
  Top Layer w6: SB13.1@2816,1951 2816,2013 2845,2042 3124,2042 3200,2118 P6.4@3200,2141.92
  Top Layer w15: P6.4@3200,2151.6 v1(3200,2199.6) P6.4@3200,2257.28 P17.8@3200,2349.6
  Bottom Layer w15: P12.4@3200,2141.92 v1(3200,2199.6) P12.4@3200,2257.28
P0.06: SB14.2 SB23.1 TP6.1 U1.8 | length 2566.8
  Top Layer w6: TP6.1@1850,1049.6 1895.6,1004 1978,1004 1993,989 1993,904.03 2028.03,869 2061.97,869 2149.97,957 2224,957 v1(2233,948) ; TP6.1@1863,1062.6 SB23.1@1863,1149.6 ; v1(2739,1110) 2778,1071 3001.01,1071 3044,1113.99 3044,1183.21 3105.32,1244.54 U1.8@3126.37,1244.54 ; v1(2766,1903.4) SB14.2@2766,1924.4
  Bottom Layer w6: v1(2233,948) 2254,927 2286.68,927 2325.68,966 2569.03,966 2680.03,1077 2706,1077 v1(2739,1110) 2766,1137 v1(2766,1903.4)
P0.06_C: P6.5 P12.5 P17.10 SB14.1 | length 794.1
  Top Layer w6: SB14.1@2766,1951 2766,2026 2794,2054 3036,2054 3100,2118 P6.5@3100,2141.92
  Top Layer w15: P6.5@3100,2141.92 v1(3100,2199.6) P6.5@3100,2257.28 P17.10@3100,2349.6
  Bottom Layer w15: P12.5@3100,2141.92 v1(3100,2199.6) P12.5@3100,2257.28
P0.07: SB15.2 SB24.1 TP7.1 U1.9 | length 2353.9
  Top Layer w6: TP7.1@1963,936.6 SB24.1@1963,849.6 2059.6,849.6 2154.96,944.96 2206.04,944.96 2224,927 2256,927 v1(2277,948) ; v1(2709,1110) 2760,1059 3006.01,1059 3056,1108.99 3056,1178.24 3106.55,1228.79 U1.9@3126.37,1228.79 ; v1(2716,1903.4) SB15.2@2716,1924.4
  Bottom Layer w6: v1(2277,948) 2307,978 2564.06,978 2675.09,1089.03 2688,1089 v1(2709,1110) 2754,1155 2754,1774 2716,1812 v1(2716,1903.4)
P0.07_C: P6.6 P12.6 P17.12 SB15.1 | length 736.4
  Top Layer w6: SB15.1@2716,1951 2716,2027 2755,2066 2947,2066 3000,2119 P6.6@3000,2141.92
  Top Layer w15: P6.6@3000,2149.6 v1(3000,2199.6) P6.6@3000,2257.28 P17.12@3000,2349.6
  Bottom Layer w15: P12.6@3000,2141.92 v1(3000,2199.6) P12.6@3000,2257.28
P0.08: SB16.2 SB25.1 TP8.1 U1.10 | length 2492.9
  Top Layer w6: TP8.1@1949.75,1049.85 TP8.1@1950,1049.6 2005,994.6 2005,909 2033,881 2057,881 2145,969 v1(2255,969) ; TP8.1@1963,1063.1 SB25.1@1963,1149.6 ; v1(2666,1903.4) SB16.2@2666,1924.4 ; v1(2679,1110) 2742,1047 3011.01,1047 3068,1103.99 3068,1173.27 3107.77,1213.04 U1.10@3126.37,1213.04
  Bottom Layer w6: v1(2255,969) 2276,990 2559.09,990 v1@2679.04,1109.96 ; v1(2666,1903.4) 2666,1845 2742,1769 2742,1160.32 2712.68,1131 2700,1131 v1(2679,1110)
P0.08_C: P6.7 P12.7 P17.14 SB16.1 | length 678.9
  Top Layer w6: SB16.1@2666,1951 2666,2020 2724,2078 2860,2078 2900,2118 P6.7@2900,2141.92
  Top Layer w15: P6.7@2900,2153.6 v1(2900,2199.6) P6.7@2900,2257.28 P17.14@2900,2349.6
  Bottom Layer w15: P12.7@2900,2141.92 v1(2900,2199.6) P12.7@2900,2257.28
P0.09: P6.8 P12.8 P17.16 R27.1 | length 1782.3
  Top Layer w6: v1(2656,996) R27.1@2683.84,996
  Top Layer w15: P6.8@2800,2141.92 v1(2800,2199.6) P6.8@2800,2257.28 P17.16@2800,2349.6
  Bottom Layer w6: v1(2656,996) 2679.74,972.26 2830.13,972.26 2844,986.13 2844,1056 2802,1098 2802,1832.01 2867,1897.03 2867,2052 2800,2119 P12.8@2800,2141.92
  Bottom Layer w15: P12.8@2800,2141.92 v1(2800,2199.6) P12.8@2800,2257.28
P0.09/NFC1: R25.2 R27.2 U1.11 | length 557.8
  Top Layer w6: R25.2@2722.69,969 2722.69,1000.69 2757,1035 3016.68,1035 3080,1098.32 3080,1168.3 3108.99,1197.29 U1.11@3126.37,1197.29
P0.10: P6.9 P12.9 P17.18 R28.1 | length 1668.5
  Top Layer w6: R28.1@2799.69,996 v1(2823,996)
  Top Layer w15: P6.9@2700,2141.92 v1(2700,2199.6) P6.9@2700,2257.28 P17.18@2700,2349.6
  Bottom Layer w6: 2790,1836.99 2790,1093 2823,1060 v1(2823,996) ; 2790,1837 2855,1902 2855,2046.82 2816.82,2085 2734,2085 P12.9@2700,2119 ; P12.9@2700,2119 P12.9@2700,2141.92 P12.9@2700,2119
  Bottom Layer w15: P12.9@2700,2141.92 v1(2700,2199.6) P12.9@2700,2257.28
P0.10/NFC2: R26.2 R28.2 U1.12 | length 515.7
  Top Layer w6: R26.2@2757.31,969 2757.31,999 2781.31,1023 3021.65,1023 3092,1093.35 3092,1163.33 3110.21,1181.55 U1.12@3126.37,1181.55
P0.11: P3.1 P9.1 P15.2 U1.14 | length 2146.5
  Top Layer w6: U1.14@3174.6,1149.07 3174.6,1124.27 3185,1113.87 v1(3185,1100.03)
  Top Layer w15: P3.1@2500,2141.92 v1(2500,2199.6) P3.1@2500,2257.28 P15.2@2500,2349.6
  Mid-Layer 2 w6: v1(2649,1110) 2706,1053 3164.03,1053 3185,1073.97 v1(3185,1100.03)
  Bottom Layer w6: P9.1@2500,2118 2628,1990 2628,1865.82 2730,1763.82 2730,1165.29 2707.71,1143 2682,1143 v1(2649,1110)
  Bottom Layer w15: P9.1@2500,2118 v1(2500,2199.6) P9.1@2500,2257.28
P0.12: P3.2 P9.2 P15.4 U1.15 | length 2468.2
  Top Layer w6: U1.15@3190.35,1149.07 3190.35,1125.52 3206,1109.87 v1(3206,1078)
  Top Layer w15: P3.2@2400,2141.92 v1(2400,2199.6) P3.2@2400,2257.28 P15.4@2400,2349.6
  Mid-Layer 2 w6: v1(2619,1110) 2688,1041 3169,1041 v1(3206,1078)
  Bottom Layer w6: v1(2619,1110) 2586,1143 2389,1143 2378,1154 2378,1454 2468,1544 2468,1760.16 2535,1827.16 2535,2022.94 2463.94,2094 2425,2094 P9.2@2400,2119 ; P9.2@2400,2119 P9.2@2400,2141.92 ; P9.2@2400,2119 P9.2@2400,2141.92 ; P9.2@2400,2119 P9.2@2400,2141.92
  Bottom Layer w15: P9.2@2400,2141.92 v1(2400,2199.6) P9.2@2400,2257.28
P0.13: P3.3 P9.3 P15.6 U1.16 U4.15 | length 3193.7
  Top Layer w6: U1.16@3206.09,1149.07 3206.09,1126.77 3227,1105.87 v1(3227,1056) ; v1(3278,534) 3283.87,539.87 U4.15@3307.89,539.87
  Top Layer w15: P3.3@2300,2141.92 v1(2300,2199.6) P3.3@2300,2257.28 P15.6@2300,2349.6
  Mid-Layer 2 w6: v1(2589,1110) 2670,1029 3200,1029 v1(3227,1056)
  Bottom Layer w6: P9.3@2300,2141.92 2300,2119 2337,2082 2458.97,2082 2523,2017.97 2523,1832.14 2456,1765.14 2456,1548.97 2366,1458.97 2366,1149 2384,1131 2568,1131 v1(2589,1110) ; v1(3227,1056) 3227,1003.82 3329,901.82 3329,572 3291,534 v1(3278,534)
  Bottom Layer w15: P9.3@2300,2141.92 v1(2300,2199.6) P9.3@2300,2257.28
P0.14: P3.4 P9.4 P15.8 U1.17 U4.3 | length 3383.4
  Top Layer w6: U1.17@3221.84,1149.07 3221.84,1128.02 3248,1101.87 v1(3248,1034) ; v1(3243.66,532) 3251.79,540.13 U4.3@3251.79,564.48
  Top Layer w15: P3.4@2200,2141.92 v1(2200,2199.6) P3.4@2200,2257.28 P15.8@2200,2349.6
  Mid-Layer 2 w6: v1(2559,1110) 2652,1017 3231,1017 v1(3248,1034)
  Bottom Layer w6: P9.4@2200,2141.92 2200,2119 2249,2070 2454,2070 2511,2013 2511,1837.11 2444,1770.11 2444,1553.94 2354,1463.94 2354,1144 2379,1119 2550,1119 v1(2559,1110) ; v1(3243.66,532) 3262.66,513 3287,513 3341,567 3341,907.13 3248,1000.13 v1(3248,1034)
  Bottom Layer w15: P9.4@2200,2141.92 v1(2200,2199.6) P9.4@2200,2257.28
P0.15: P3.5 P9.5 P15.10 U1.18 U4.7 | length 3908.2
  Top Layer w6: v1(2547,1011) 2613.75,944.25 2613.75,854.25 2643,825 v1(2699,825) ; v1(2781,825) 2821.99,784 3011,784 3045,818 3045,897.91 3122.09,975 3242,975 3269,1002 v1(3269,1056) 3269,1097.87 3237.59,1129.28 U1.18@3237.59,1149.07 ; v1@3177.79,524.13 U4.7@3211.44,524.13
  Top Layer w15: P3.5@2100,2141.92 v1(2100,2199.6) P3.5@2100,2257.28 P15.10@2100,2349.6
  Bottom Layer w6: P9.5@2100,2141.92 2114.66,2141.92 2198.58,2058 2449.03,2058 2499,2008.03 2499,1842.08 2432,1775.08 2432,1558.91 2342,1468.91 2342,1138.73 2373.73,1107 2451,1107 v1(2547,1011) ; v1(2699,825) v1(2781,825) ; v1(3177.66,524) 3200.66,501 3292,501 3353,562 3353,912.39 3269,996.39 v1(3269,1056)
  Bottom Layer w15: P9.5@2100,2141.92 v1(2100,2199.6) P9.5@2100,2257.28
P0.16: P3.6 P9.6 P15.12 U1.19 U4.11 | length 3953.1
  Top Layer w6: v1(2517,1011) 2538,990 2551.03,990 2601.75,939.28 2601.75,849.28 2656.03,795 v1(2699,795) ; v1(2781,795) 2803.99,772 3015.97,772 3057,813.03 3057,892.94 3127.06,963 3246.97,963 3290,1006.03 v1(3290,1034) 3290,1066 3281,1075 3281,1102.84 3253.34,1130.5 U1.19@3253.34,1149.07 ; v1(3260.66,468) 3267.54,474.88 U4.11@3267.54,499.52
  Top Layer w15: P3.6@2000,2141.92 v1(2000,2199.6) P3.6@2000,2257.28 P15.12@2000,2349.6
  Bottom Layer w6: P9.6@2000,2141.92 2000,2119.6 2073.6,2046 2444.06,2046 2487,2003.06 2487,1847.05 2420,1780.05 2420,1563.88 2330,1473.88 2330,1133.76 2368.76,1095 2433,1095 v1(2517,1011) ; v1(2699,795) v1@2771,795 ; v1(3260.66,468) 3281.66,489 3297,489 3365,557 3365,917.48 3290,992.48 v1(3290,1034)
  Bottom Layer w15: P9.6@2000,2141.92 v1(2000,2199.6) P9.6@2000,2257.28
P0.17: P3.7 P9.7 P15.14 SB30.1 U1.20 U5.15 | length 4954
  Top Layer w6: P3.7@1908,2109 v1(1933,2109) ; SB30.1@1909.52,1928.77 1909.94,1928.77 v1(1932.94,1905.77) ; v1(2487,1011) 2520,978 2546,978 2589.71,934.29 2589.71,844.29 2669,765 v1(2699,765) ; v1(2781,765) 2794,765 2798.99,760 3020.94,760 3069,808.06 3069,887.97 3132.03,951 3252.68,951 3311,1009.32 3311,1062.03 3293,1080.03 3293,1107.81 3269.09,1131.72 U1.20@3269.09,1149.07 ; v1(3629.94,2033) 3675,2033 3681.13,2026.87 U5.15@3681.13,2010.23
  Top Layer w15: P3.7@1900,2141.92 P3.7@1900,2257.28 P15.14@1900,2349.6
  Mid-Layer 2 w6: v1(1932.94,1905.77) v1(1933,2109) ; v1(2466,1894) 2554,1982 3566,1982 3617,2033 v1(3629.94,2033)
  Bottom Layer w6: P9.7@1900,2141.92 1900,2118 1909,2109 v1(1933,2109) 2008,2034 2437.94,2034 2475,1996.94 2475,1903 v1(2466,1894) 2466,1843.32 2408,1785.32 2408,1568.85 2318,1478.85 2318,1128.79 2363.79,1083 2415,1083 v1(2487,1011) ; v1(2699,765) v1@2771,765
  Bottom Layer w15: P9.7@1900,2141.92 v1(1900,2199.6) P9.7@1900,2257.28
P0.18: P3.8 P9.8 P15.16 P18.6 SB26.1 U1.21 U5.3 | length 6304.4
  Top Layer w6: SB26.1@1670.02,713 v1(1804.02,713) ; v1(2050,904) 2062.68,904 2148.68,990 2435.7,990 2456.7,1011 v1(2457,1011) 2502,966 2541,966 2577.71,929.29 2577.71,839.28 2682,735 v1(2699,735) ; v1(2412,680.23) P18.6@2412,743 ; v1(2781,735) 2794,748 3025.91,748 3081,803.09 3081,883 3137,939 3257.65,939 3323,1004.35 3323,1067 3305,1085 3305,1112.78 3284.83,1132.94 U1.21@3284.83,1149.07 ; v1(3626,1942) 3638.13,1954.13 U5.3@3656.52,1954.13
  Top Layer w15: P3.8@1800,2141.92 v1(1800,2199.6) P3.8@1800,2257.28 P15.16@1800,2349.6
  Mid-Layer 2 w6: v1(2412,680.23) 2433,701.23 2665.23,701.23 v1(2699,735) ; v1(2454,1922) 2526,1994 3561,1994 3621.07,2054.07 3658.99,2054.07 3677,2036.06 3677,1993 v1(3626,1942)
  Bottom Layer w6: P9.8@1800,2141.92 1800,2118.6 1896.6,2022 2432.97,2022 2463,1991.97 2463,1931 v1(2454,1922) 2445,1913 2445,1839.32 2396,1790.32 2396,1573.82 2306,1483.82 2306,1123.82 2358.82,1071 2397,1071 v1(2457,1011) ; v1(1804.02,713) 1946,713 2050,817 v1(2050,904) ; v1(2699,735) v1@2771,735
  Bottom Layer w15: P9.8@1800,2141.92 v1(1800,2199.6) P9.8@1800,2257.28
P0.19: P4.1 P10.1 P16.2 U1.22 U5.7 | length 4897.1
  Top Layer w6: P4.1@1640,2119.77 P4.1@1640,2141.92 ; U1.22@3300.58,1149.07 3300.58,1134.17 3326,1108.75 v1(3326,1096) ; v1(3689,1944) 3696.87,1936.13 U5.7@3696.87,1913.77
  Top Layer w15: P4.1@1640,2141.92 v1(1640,2199.6) P4.1@1640,2257.28 P16.2@1640,2349.6
  Mid-Layer 2 w6: v1(2427,1011) 2517,921 2858.33,921 2942.33,1005 3310,1005 3326,1021 v1(3326,1096) ; v1(2442,1950) 2498,2006 3556.03,2006 3616.1,2066.07 3663.96,2066.07 3689,2041.03 v1(3689,1944)
  Bottom Layer w6: P10.1@1640,2141.92 1640,2119.77 1749.77,2010 2428,2010 2451,1987 2451,1959 v1(2442,1950) 2433,1941 2433,1844.32 2384,1795.32 2384,1578.79 2294,1488.79 2294,1117.82 2352.82,1059 2379,1059 v1(2427,1011)
  Bottom Layer w15: P10.1@1640,2141.92 v1(1640,2199.6) P10.1@1640,2257.28
P0.20: P4.2 P10.2 P16.4 U1.23 U5.11 | length 5041.8
  Top Layer w6: P4.2@1540,2118.6 P4.2@1540,2141.92 ; U1.23@3316.33,1149.07 3316.33,1135.39 3347,1104.72 v1(3347,1074) ; U5.11@3721.48,1969.87 3743.13,1969.87 v1(3751,1962)
  Top Layer w15: P4.2@1540,2141.92 v1(1540,2199.6) P4.2@1540,2257.28 P16.4@1540,2349.6
  Mid-Layer 2 w6: v1(2397,1011) 2499,909 2863.31,909 2947.31,993 3314.97,993 3347,1025.03 v1(3347,1074) ; v1(2430,1978) 2470,2018 3551.06,2018 3611.13,2078.07 3668.93,2078.07 3701,2046 3701,2012 v1(3751,1962)
  Bottom Layer w6: P10.2@1540,2141.92 1540,2118.6 1660.6,1998 2410,1998 v1(2430,1978) 2421,1969 2421,1850 2372,1801 2372,1583.76 2282,1493.76 2282,1112.85 2347.85,1047 2361,1047 v1(2397,1011)
  Bottom Layer w15: P10.2@1540,2141.92 v1(1540,2199.6) P10.2@1540,2257.28
P0.21: P6.3 P12.3 P17.6 P18.10 SB17.2 SB27.1 TP11.1 U1.24 | length 4804.7
  Top Layer w6: SB27.1@1670.02,763 1711.02,804 2049,804 2139,894 v1(2197,894) ; TP11.1@2150,649.6 2213.4,713 v1(2281,713) P18.10@2312,713 ; SB17.2@2153,1071.4 2158.86,1065.54 2213.4,1011 v1(2277,1011) ; U1.24@3332.08,1149.07 3332.08,1136.61 3368,1100.69 v1(3368,1052)
  Top Layer w15: P6.3@3300,2141.92 v1(3300,2199.6) P6.3@3300,2257.28 P17.6@3300,2349.6
  Mid-Layer 2 w6: v1(2828,876) 2849,897 2868.31,897 2952.31,981 3320,981 3368,1029 v1(3368,1052)
  Bottom Layer w6: v1(2277,1011) 2239,1011 2188,960 2188,903 v1(2197,894) 2188,885 2188,806 v1(2281,713) 2858.03,713 2903,757.97 2903,801 v1(2828,876) 2882,930 2882,1035 2814,1103 2814,1735.31 2965,1886.31 2965,1978.04 3061.96,2075 3257,2075 3300,2118 P12.3@3300,2141.92
  Bottom Layer w15: P12.3@3300,2141.92 v1(3300,2199.6) P12.3@3300,2257.28
P0.22: P4.3 P10.3 P16.6 U1.27 | length 3780
  Top Layer w6: U1.27@3364.56,1213.04 3377.32,1213.04 3413,1177.36 v1(3413,1103.03)
  Top Layer w15: P4.3@1440,2118.6 v1(1440,2199.6) P4.3@1440,2257.28 P16.6@1440,2349.6
  Mid-Layer 2 w6: v1(2367,1011) 2481,897 2775,897 2817,855 2837,855 v1(2858,876) 2879,855 2926.74,855 3016.74,945 3335,945 3413,1023 v1(3413,1103.03)
  Bottom Layer w6: P10.3@1440,2141.92 1440,2118.6 1560.6,1998 1643.38,1998 1655.38,1986 2292.62,1986 2360,1918.62 2360,1799 ; 2360,1806.16 2360,1588.73 2270,1498.73 2270,1107.88 v1(2367,1011)
  Bottom Layer w15: P10.3@1440,2141.92 v1(1440,2199.6) P10.3@1440,2257.28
